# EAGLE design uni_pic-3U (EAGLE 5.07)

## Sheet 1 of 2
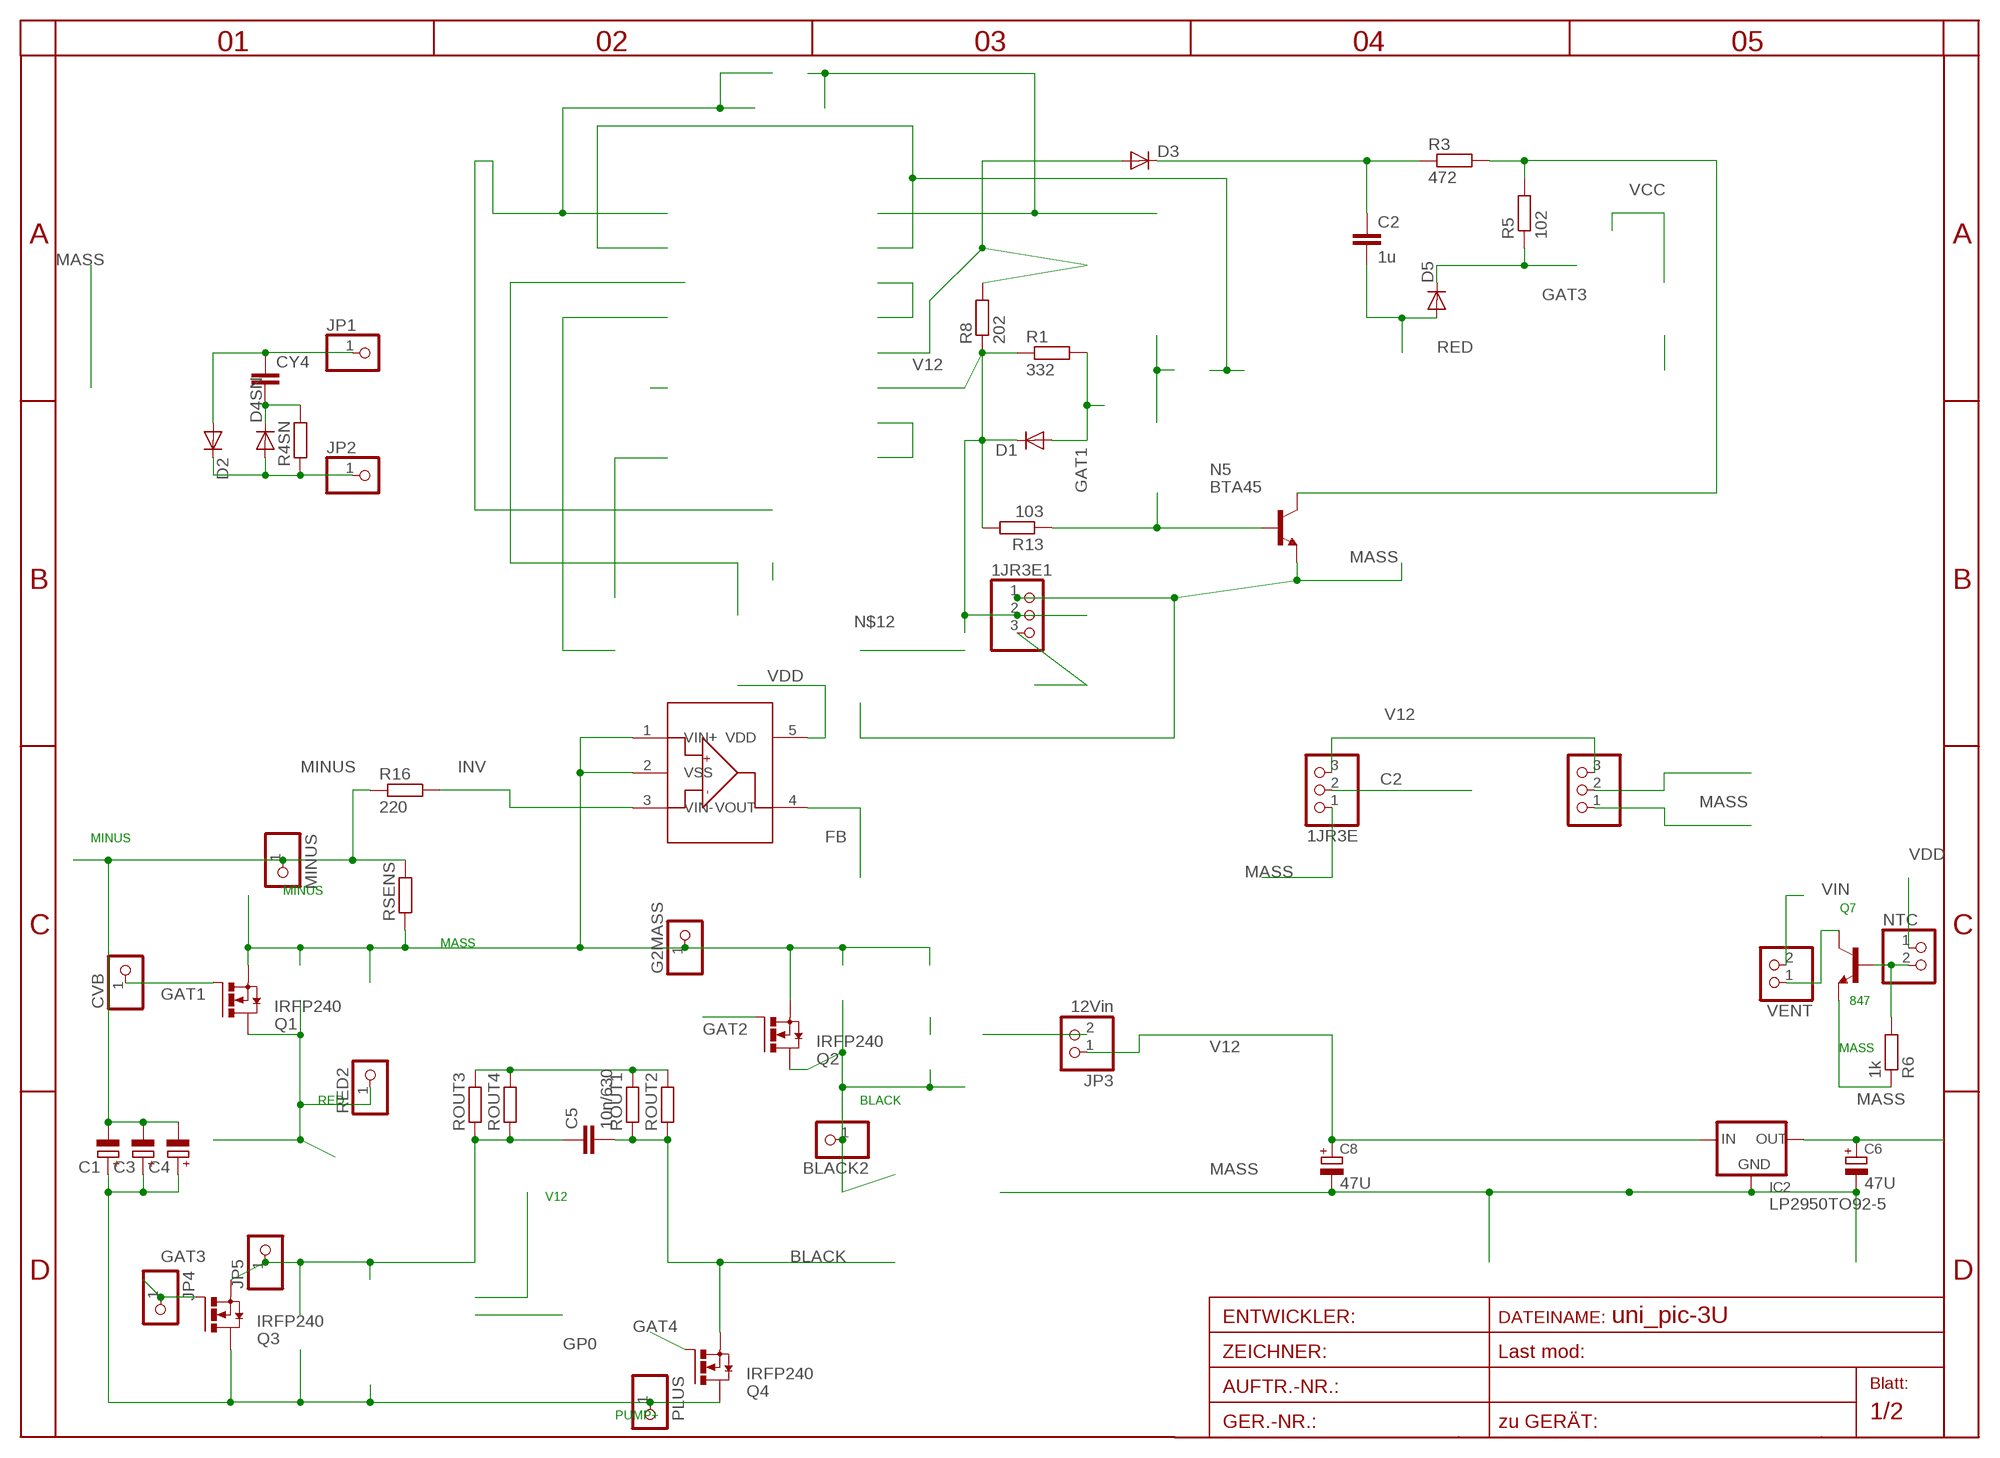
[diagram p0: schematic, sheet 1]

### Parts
1JR3E  PINHD-1X3  [1X03]
1JR3E1  PINHD-1X3  [1X03]
2JR4E3  PINHD-1X3  [1X03]
BLACK2  PINHD-1X12MM3  [1X2MM3]
C1  CPOL-EUE5-13  [E5-13]
C2  1u  C-EUC1206  [C1206]
C3  CPOL-EUE5-13  [E5-13]
C4  CPOL-EUE5-13  [E5-13]
C5  10n/630  C-EU075-042X103  [C075-042X103]
C6  47U  CPOL-EUE2.5-6  [E2,5-6]
C8  47U  CPOL-EUE2.5-6  [E2,5-6]
CVB  PINHD-1X11MM0  [1X1MM0]
CY4  CXXC10B5  [XC10B5]
D1  DIODE-MINIMELF  [MINIMELF]
D2  DIODE-SMC  [SMC]
D3  DIODE-SMA-DO214  [SMA-DO214AC]
D4SN  DIODE-P1-10  [P1-10]
D5  DIODE-MINIMELF  [MINIMELF]
G2MASS  PINHD-1X11MM0  [1X1MM0]
IC2  LP2950TO92-5  [T092-5]
JP1  PINHD-1X11MM0  [1X1MM0]
JP2  PINHD-1X11MM0  [1X1MM0]
JP3  12Vin  PINHD-1X2STR  [1X02]
JP4  PINHD-1X11MM0  [1X1MM0]
JP5  PINHD-1X11MM0  [1X1MM0]
MINUS  PINHD-1X12MM3  [1X2MM3]
N5  BTA45  SMBTA45HV  [SOT23HV]
NTC  PINHD-1X2STR  [1X02]
OP1  MCP6001U  [SOT23-5L]
PLUS  PINHD-1X12MM3  [1X2MM3]
Q1  IRFP240  [TO247BV]
Q2  IRFP240  [TO247BV]
Q3  IRFP240  [TO247BV]
Q4  IRFP240  [TO247BV]
Q7  847  BC847ALT1SMD  [SOT23]
R1  332  R-EU_R0805  [R0805]
R3  472  R-EU_R0805  [R0805]
R4SN  R-EU_0207/10  [0207/10]
R5  102  R-EU_R1206  [R1206]
R6  1k  R-EU_R0805  [R0805]
R8  202  R-EU_R0805  [R0805]
R13  103  R-EU_0207/15  [0207/15]
R16  220  R-EU_0207/30  [0207/30]
RED2  PINHD-1X12MM3  [1X2MM3]
ROUT1  R-EU_0204/7  [0204/7]
ROUT2  R-EU_0204/7  [0204/7]
ROUT3  R-EU_0204/7  [0204/7]
ROUT4  R-EU_0204/7  [0204/7]
RSENS  R-EU_0204/7  [0204/7]
VENT  PINHD-1X2STR  [1X02]

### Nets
BLACK: BLACK2.1 C5.2 Q2.D Q4.S ROUT1.1 ROUT2.1
C1: 2JR4E3.2 ; also sheet 2
C2: 1JR3E1.2 1JR3E.2 D1.C R1.1 R8.1 R13.2 ; also sheet 2
DRAIN: D2.C D4SN.A JP2.1 R4SN.1
FB: OP1.4(VOUT) ; also sheet 2
GAT1: CVB.1 D1.A Q1.G R1.2
GAT2: Q2.G
GAT3: D5.C JP4.1 Q3.G R5.1
GAT4: Q4.G
INV: OP1.3(VIN-) R16.2 ; also sheet 2
MASS: 1JR3E1.1 1JR3E.1 2JR4E3.1 C6.- C8.- G2MASS.1 IC2.2(GND) JP3.2 N5.2(E) OP1.1(VIN+) OP1.2(VSS) Q1.S Q2.S Q7.2(E) R6.1 RSENS.1 ; also sheet 2
MINUS: C1.- C3.- C4.- MINUS.1 R16.1 RSENS.2
N$4: C2.1 D3.K(C) R3.1
N$7: ROUT1.2 ROUT2.2 ROUT3.2 ROUT4.2
N$8: N5.3(C) R3.2 R5.2
N$9: NTC.2 Q7.1(B) R6.2
N$10: Q7.3(C) VENT.1
N$17: N5.1(B) R13.1
PUMP+: C1.+ C3.+ C4.+ PLUS.1 Q3.D Q4.D ; also sheet 2
RED: C2.2 C5.1 D5.A JP5.1 Q1.D Q3.S RED2.1 ROUT3.1 ROUT4.1
SNUB2: CY4.2 D4SN.C R4SN.2
SOURCE: CY4.1 D2.A JP1.1
V12: 1JR3E1.3 1JR3E.3 2JR4E3.3 C8.+ D3.A IC2.3(IN) JP3.1 R8.2
VDD: C6.+ IC2.1(OUT) NTC.1 OP1.5(VDD) ; also sheet 2
VIN: VENT.2

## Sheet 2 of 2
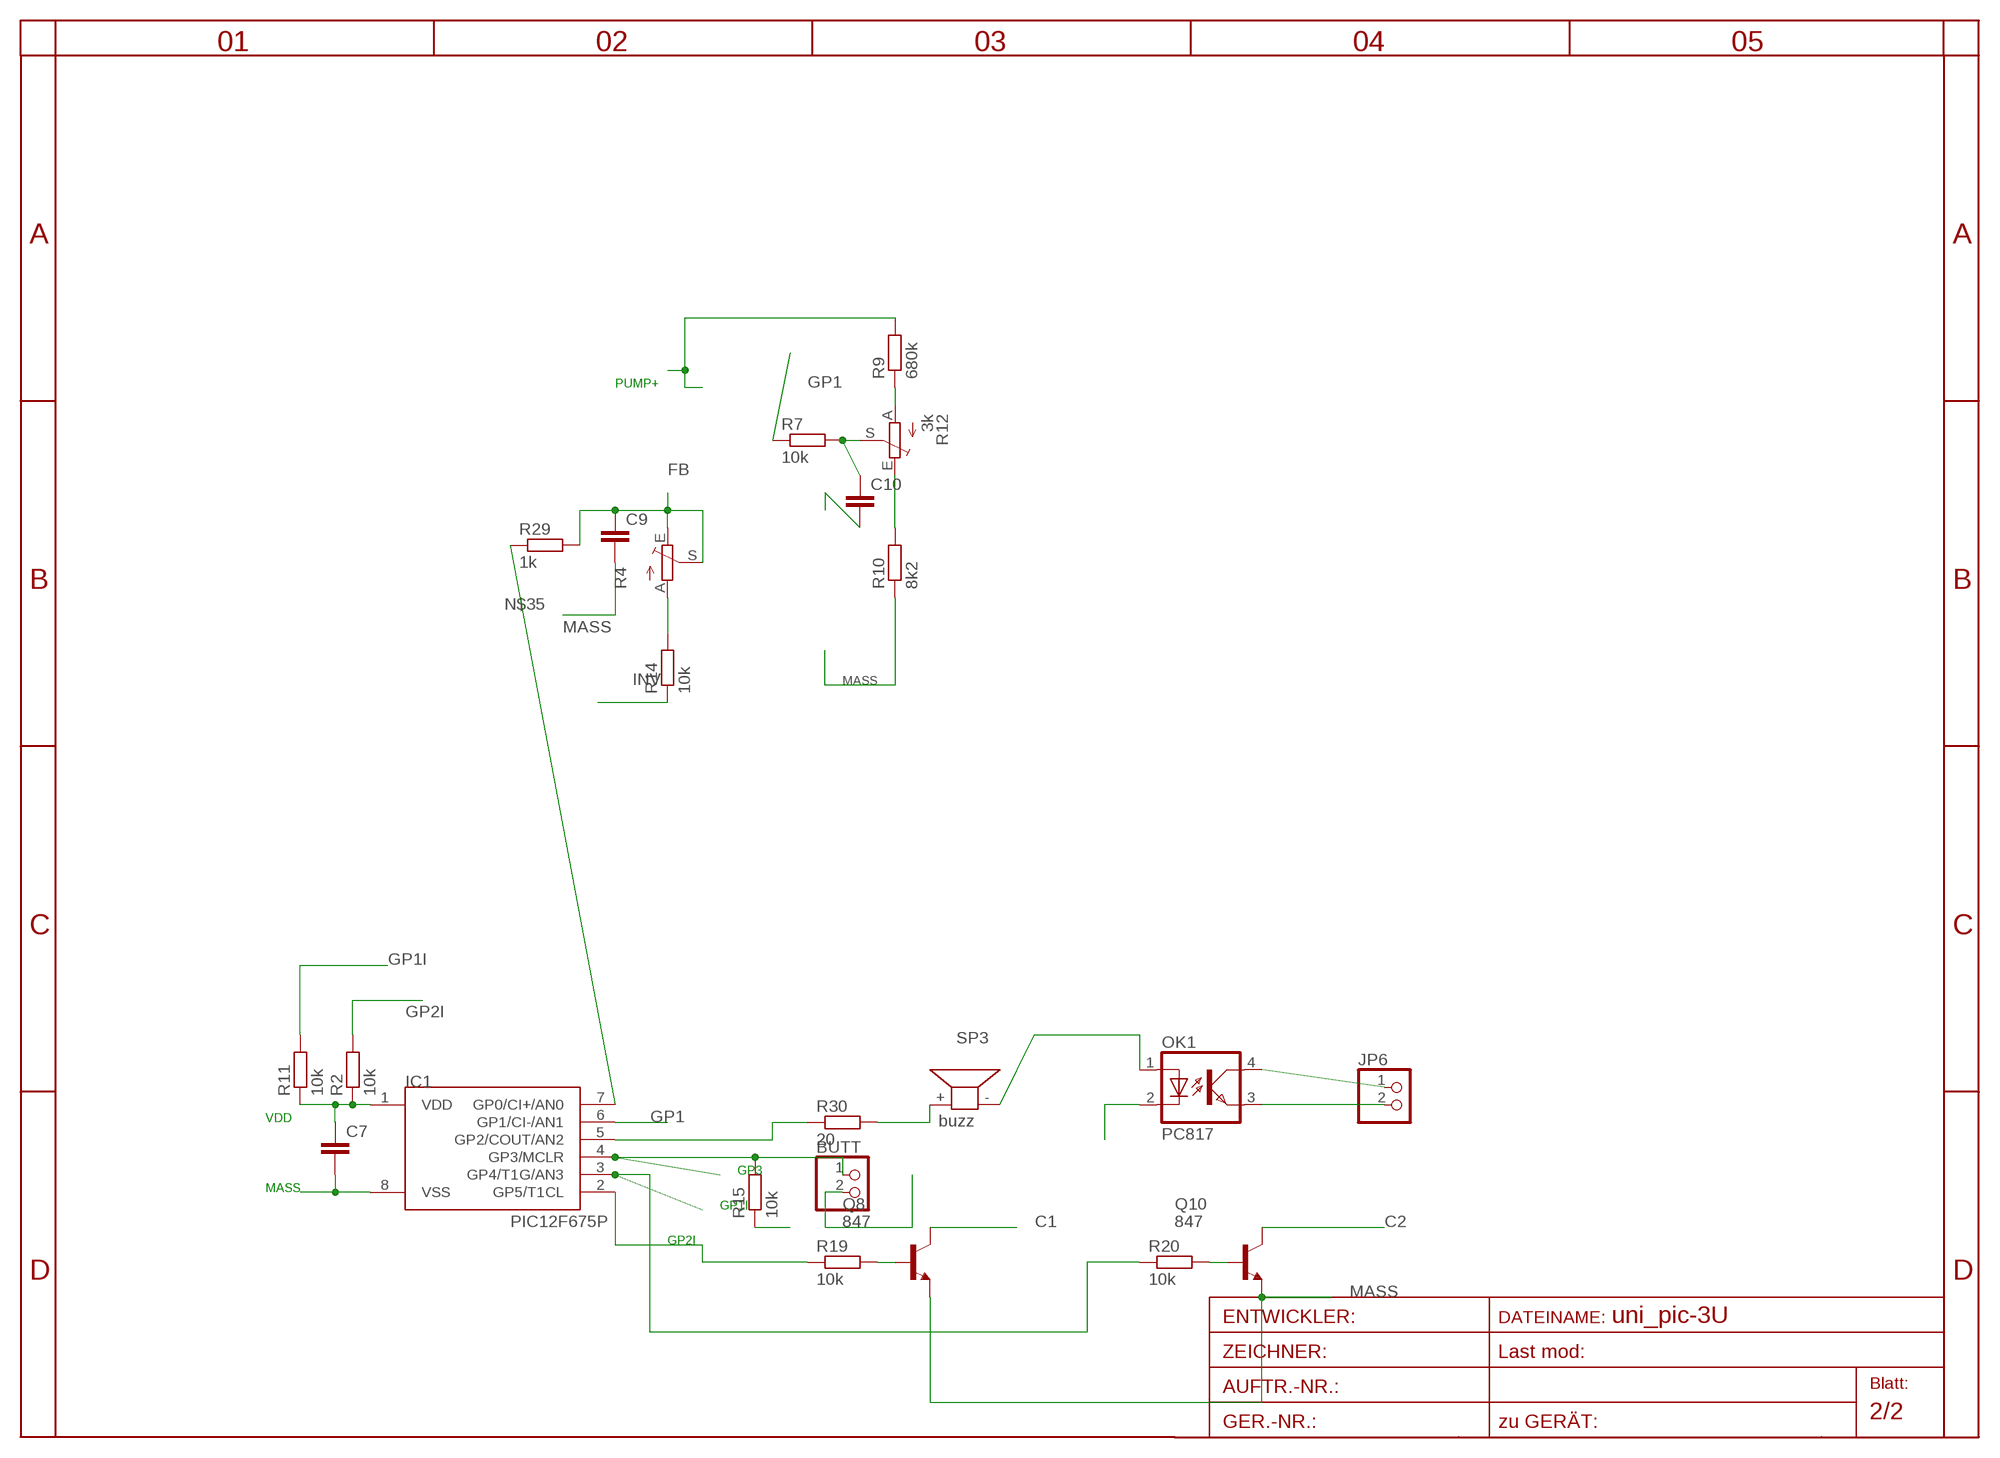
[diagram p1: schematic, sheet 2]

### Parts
BUTT  PINHD-1X2STR  [1X02]
C7  C-EUC0805  [C0805]
C9  C-EUC0805  [C0805]
C10  C-EUC0805  [C0805]
IC1  PIC12F675P  [DIL8]
JP6  PINHD-1X2STR  [1X02]
OK1  PC817  [DIL04]
Q8  847  BC847ALT1SMD  [SOT23]
Q10  847  BC847ALT1SMD  [SOT23]
R2  10k  R-EU_R0805  [R0805]
R4  TRIM_EU-CA6V  [CA6V]
R7  10k  R-EU_R0805  [R0805]
R9  680k  R-EU_0207/30  [0207/30]
R10  8k2  R-EU_R0805  [R0805]
R11  10k  R-EU_R0805  [R0805]
R12  3k  TRIM_EU-CA6V  [CA6V]
R14  10k  R-EU_R0805  [R0805]
R15  10k  R-EU_R0805  [R0805]
R19  10k  R-EU_R0805  [R0805]
R20  10k  R-EU_R0805  [R0805]
R29  1k  R-EU_R0805  [R0805]
R30  20  R-EU_R0805  [R0805]
SP3  buzz  KSS12017MM  [KSS1202]

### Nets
C1: Q8.3(C) ; also sheet 1
C2: Q10.3(C) ; also sheet 1
FB: C9.1 R4.E R4.S R29.2 ; also sheet 1
GP0I: IC1.5(GP2/COUT/AN2) R30.1
GP1: IC1.6(GP1/CI-/AN1) R7.1
GP1I: IC1.3(GP4/T1G/AN3) R11.2 R20.1
GP2I: IC1.2(GP5/T1CL) R2.2 R19.1
GP3: BUTT.1 IC1.4(GP3/MCLR) R15.2
INV: R14.1 ; also sheet 1
MASS: BUTT.2 C7.2 C9.2 C10.2 IC1.8(VSS) OK1.2(C) Q8.2(E) Q10.2(E) R10.1 ; also sheet 1
N$1: R4.A R14.2
N$5: JP6.2 OK1.3(EMIT)
N$22: Q10.1(B) R20.2
N$28: Q8.1(B) R19.2
N$29: R10.2 R12.E
N$30: R9.1 R12.A
N$31: C10.1 R7.2 R12.S
N$32: JP6.1 OK1.4(COL)
N$33: R30.2 SP3.+
N$34: OK1.1(A) SP3.-
N$35: IC1.7(GP0/CI+/AN0) R29.1
PUMP+: R9.2 ; also sheet 1
VDD: C7.1 IC1.1(VDD) R2.1 R11.1 R15.1 ; also sheet 1

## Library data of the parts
1JR3E 1JR3E1 2JR4E3 = pinhead:PINHD-1X3: PIN HEADER
BLACK2 CVB G2MASS JP1 JP2 JP4 JP5 MINUS PLUS RED2 = pinhead:PINHD-1X1: PIN HEADER
BUTT JP3 JP6 NTC VENT = pinhead:PINHD-1X2: PIN HEADER
C1 C3 C4 = rcl:CPOL-EU: POLARIZED CAPACITOR, European symbol
C2 C5 C7 C9 C10 = rcl:C-EU: CAPACITOR, European symbol
C6 C8 = rcl-2:CPOL-EU: POLARIZED CAPACITOR, European symbol
CY4 = rcl:CX: X CAPACITOR
D1-D3 D4SN D5 = diode:DIODE-: DIODE
IC1 = microchip-5:PIC12F6*: uPC nW 1k Program Flash memory 2x Timer Comparator 10b A/D converter/ 4xIN
IC2 = v-reg:LP2950?*: Source: http://cache.national.com/ds/LP/LP2950.pdf
N5 = transistor-npn:SMBTA45
OK1 = optocoupler:PC817: SHARP OPTO COUPLER
OP1 = microchip-3:MCP6001U
Q1-Q4 = transistor-power:IRFP240: HEXFET Power MosFet Source: http://www.irf.com/
Q7 Q8 Q10 = transistor-npn:BC847*: NPN Transistor
R1 R3 R4SN R5 R6 R8 R13 R14 ROUT1-ROUT4 RSENS = rcl:R-EU_: RESISTOR, European symbol
R2 R7 R9-R11 R15 R16 R19 R20 R29 R30 = rcl-2:R-EU_: RESISTOR, European symbol
R4 R12 = pot:TRIM_EU-: POTENTIOMETER
SP3 = buzzer:KSS1201: SPEAKER

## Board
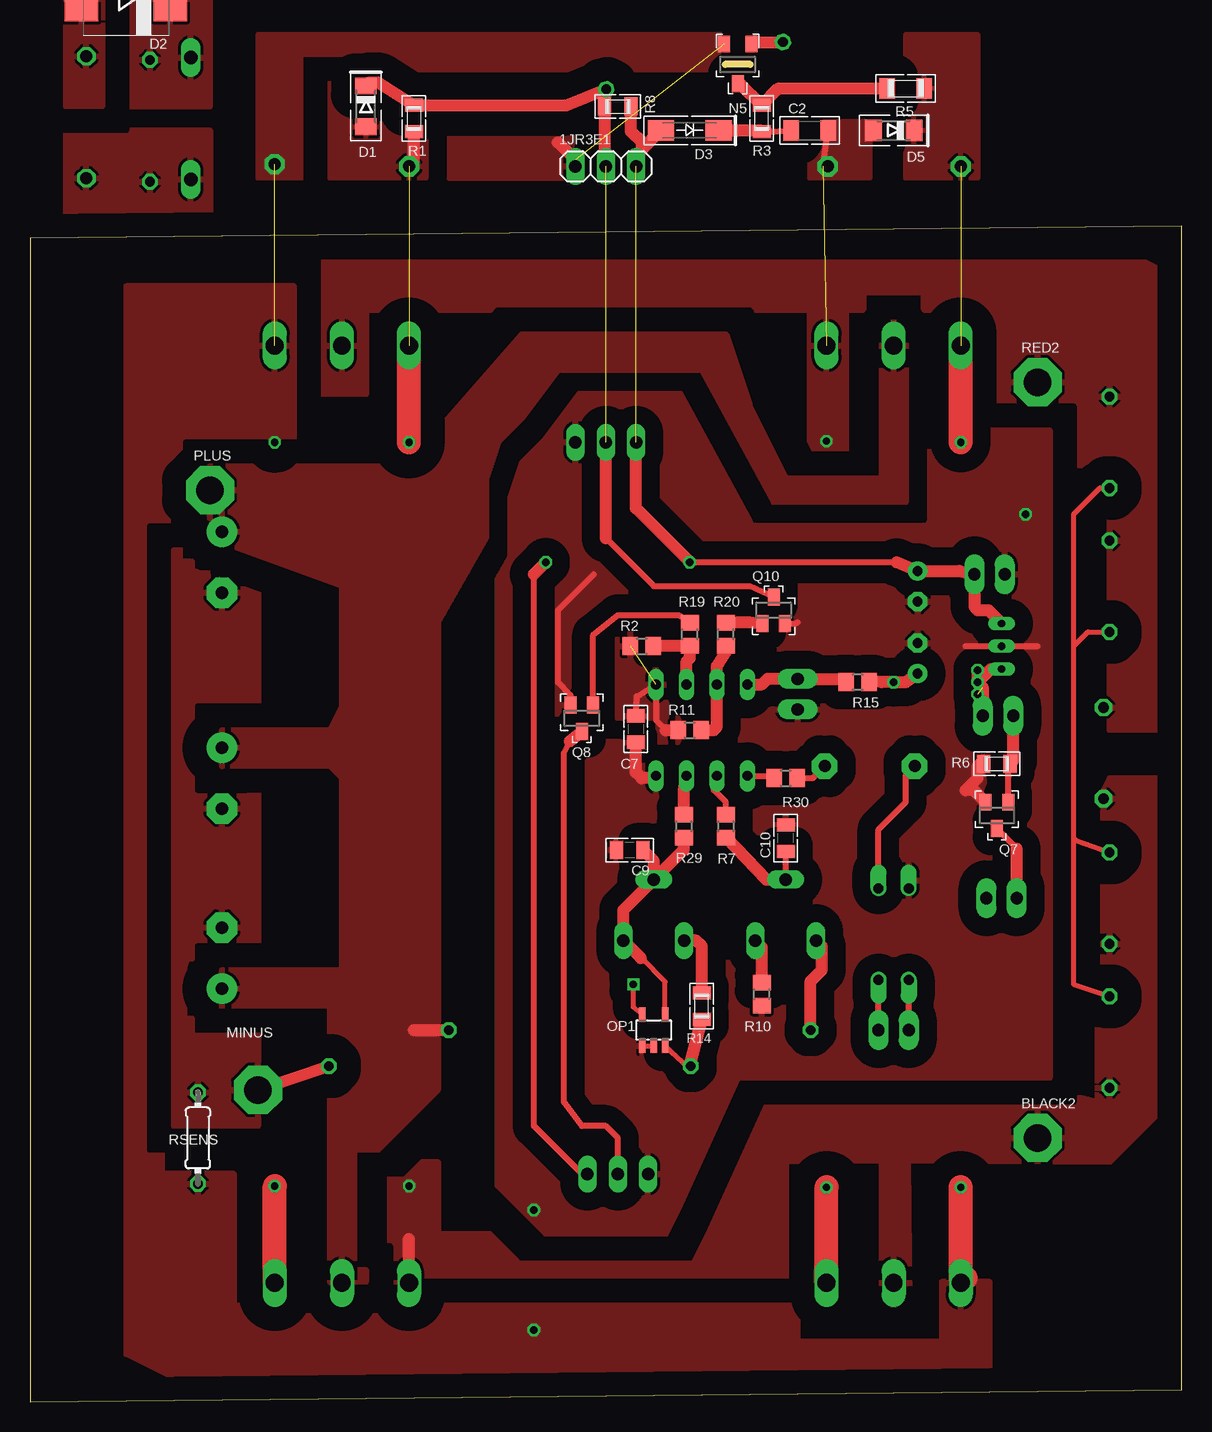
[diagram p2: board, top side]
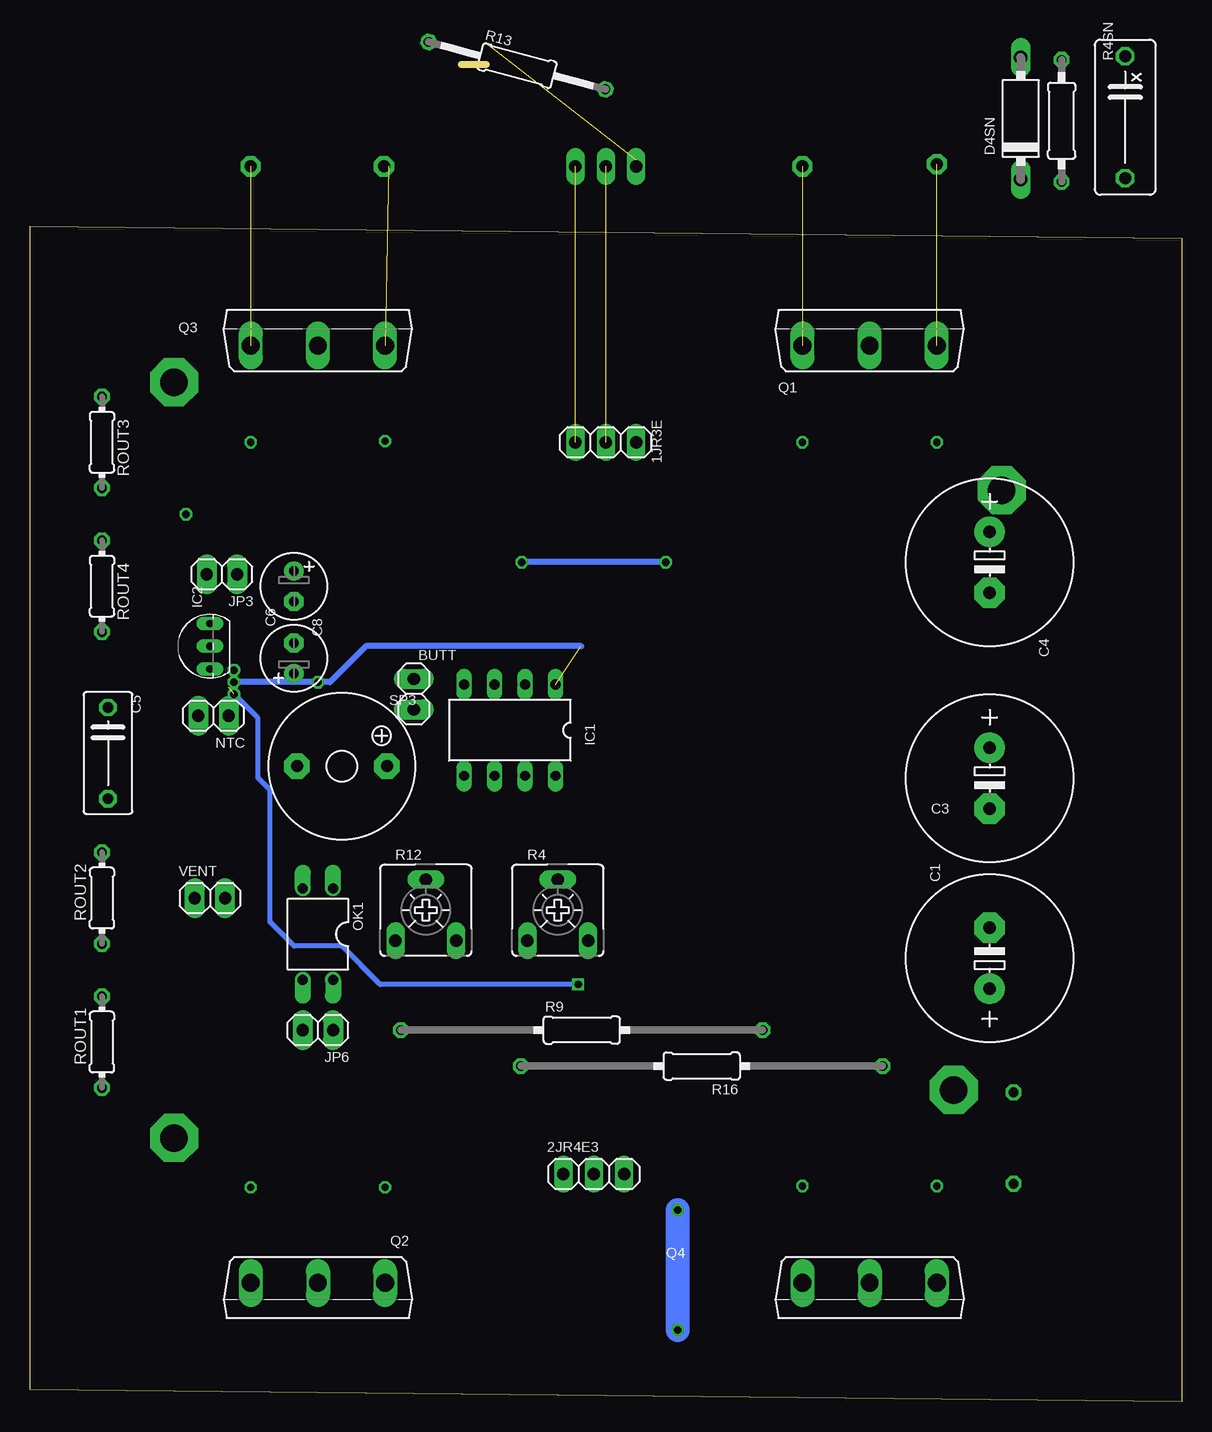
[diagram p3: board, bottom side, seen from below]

Size 96 x 98 mm. Coordinates in mm from the lower left corner, seen from the top.
Outline: 0,0 96,1 96,98 0,97 0,0
Copper layers (1*16): Top 0.035mm / dielectric 1.5mm / Bottom 0.035mm
Design rules "default *": minimum track width 10mil, minimum drill 20mil, track to track 8mil, track to pad 8mil, pad to pad 8mil, via to via 8mil, smd to smd 8mil, copper to edge 40mil, drill to drill 8mil, minimum pad ring 10mil, minimum via ring 8mil, stop-mask expansion 4mil, vias tented up to drill 0mil, thermal gap 10mil

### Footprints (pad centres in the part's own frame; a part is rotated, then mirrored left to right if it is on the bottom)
1X03 = drill 1.016 long: 1 -2.54,0; 2 0,0; 3 2.54,0
1X2MM3 = drill 2.3 pad 4 octagon: 1 0,0
1X02 = drill 1.016 pad 1.676 long: 1 -1.27,0; 2 1.27,0
E5-13 = drill 1.016 pad 2.54 round: + -2.54,0 | drill 1.016 pad 2.54 octagon: - 2.54,0
C1206 = smd 1.3 x 1.7: 1 -1.55,0; 2 1.55,0
C075-042X103 = drill 0.914 octagon: 1 -3.81,0; 2 3.81,0
E2,5-6 = drill 0.813 pad 1.6 round: + -1.27,0 | drill 0.813 pad 1.6 octagon: - 1.27,0
C0805 = smd 1.1 x 1.5: 1 -1.1,0; 2 1.1,0
1X1MM0 = drill 1 pad 1.676 octagon: 1 0,0
XC10B5 = drill 1.016 octagon: 1 -5.08,0; 2 5.08,0
MINIMELF = smd 1.4 x 1.8: A 1.7,0; C -1.7,0
SMC = smd 2.8 x 3.8: A 3.7,0; C -3.7,0
SMA-DO214AC = smd 2.2 x 1.7: A 2.4,0; K -2.4,0
P1-10 = drill 1.118 long: A 5.08,0; C -5.08,0
DIL8 = drill 0.8 long: 1 -3.81,-3.81; 2 -1.27,-3.81; 3 1.27,-3.81; 4 3.81,-3.81; 5 3.81,3.81; 6 1.27,3.81; 7 -1.27,3.81; 8 -3.81,3.81
T092-5 = drill 0.6 pad 0.813 long: 1 -1.905,0; 2 0,0; 3 1.905,0
SOT23HV = smd 1 x 1.4: 1 -1.15,-1.7; 2 1.15,-1.7; 3 0,1.6
DIL04 = drill 0.813 offset: 1 -1.27,-3.81; 2 1.27,-3.81; 3 1.27,3.81; 4 -1.27,3.81
SOT23-5L = smd 0.55 x 1.2: 1 -0.95,-1.3; 2 0,-1.3; 3 0.95,-1.3; 4 0.95,1.3; 5 -0.95,1.3
TO247BV = drill 1.499 long: D 0,-2.921; G -5.588,-2.921; S 5.588,-2.921
SOT23 = smd 1 x 1.4: 1 -0.95,-1.1; 2 0.95,-1.1; 3 0,1.1
R0805 = smd 1.1 x 1.5: 1 -1.1,0; 2 1.1,0
R0805' = smd 1.3 x 1.5: 1 -0.95,0; 2 0.95,0
CA6V = drill 1.016 long: A -2.54,-2.54; E 2.54,-2.54; S 0,2.54
0207/10 = drill 0.813 octagon: 1 -5.08,0; 2 5.08,0
R1206 = smd 1.3 x 1.7: 1 -1.55,0; 2 1.55,0
0207/30 = drill 0.813 octagon: 1 -15.08,0; 2 15.08,0
0207/15 = drill 0.813 octagon: 1 -7.62,0; 2 7.62,0
0204/7 = drill 0.813 octagon: 1 -3.81,0; 2 3.81,0
KSS1202 = drill 1 pad 2.159 octagon: + 3.75,0; - -3.75,0

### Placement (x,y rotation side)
1JR3E  48,80 180 bottom
1JR3E1  48,103 0 top  (outside the outline)
2JR4E3  49,19 0 bottom
BLACK2  84,22 0 top
BUTT  64,59 270 bottom
C1  16,37 90 bottom
C2  65,106 0 top  (outside the outline)
C3  16,52 270 bottom
C4  16,70 270 bottom
C5  89.5,54.1 270 bottom
C6  74,62 90 bottom
C7  50.5,56.1 270 top
C8  74,68 270 bottom
C9  50,46 180 top
C10  63,47 90 top
CVB  31.6,103 0 top  (outside the outline)
CY4  not placed on the board
D1  28,108 270 top  (outside the outline)
D2  not placed on the board
D3  55,106 180 top  (outside the outline)
D4SN  not placed on the board
D5  not placed on the board
G2MASS  not placed on the board
IC1  56,56 180 bottom
IC2  81,63 90 bottom
JP1  not placed on the board
JP2  not placed on the board
JP3  80,69 180 bottom
JP4  not placed on the board
JP5  66.5,103 180 top  (outside the outline)
JP6  72,31 180 bottom
MINUS  19,26 0 top
N5  59,111.5 180 top  (outside the outline)
NTC  80.7,57.2 180 bottom
OK1  72,39 180 bottom
OP1  52,31 0 top
PLUS  15,76 0 top
Q1  26,91 0 bottom
Q2  72,7 180 bottom
Q3  72,91 0 bottom
Q4  26,7 180 bottom
Q7  80.6,48.9 180 top
Q8  46,57 180 top
Q10  62,66 0 top
R1  32,107 270 top  (outside the outline)
R2  10k  [R0805']  51,63 0 top
R3  61,107 90 top  (outside the outline)
R4  52,41 0 bottom
R4SN  not placed on the board
R5  73,109.5 180 top  (outside the outline)
R6  80.6,53.2 0 top
R7  10k  [R0805']  58,48 270 top
R8  49,108 0 top  (outside the outline)
R9  50,31 0 bottom
R10  8k2  [R0805']  61,34 90 top
R11  10k  [R0805']  55,56 0 top
R12  63,41 0 bottom
R13  55.4,111.4 345 bottom  (outside the outline)
R14  56,33 90 top
R15  10k  [R0805']  69,60 180 top
R16  40,28 180 bottom
R19  10k  [R0805']  55,64 90 top
R20  10k  [R0805']  58,64 90 top
R29  1k  [R0805']  54.5,48 270 top
R30  20  [R0805']  63,52 0 top
RED2  84,85 0 top
ROUT1  90,30 90 bottom
ROUT2  90,42 90 bottom
ROUT3  90,80 270 bottom
ROUT4  90,68 270 bottom
RSENS  14,22 90 top
SP3  70,53 0 bottom
VENT  81,42 0 bottom

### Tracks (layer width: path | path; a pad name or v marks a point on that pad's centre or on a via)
BLACK  (via drill 0.6 pad 1)
  Top 1: Q4.S 31.59,13.59
  other vias: 31.6,18
  pour Top (isolate 2, rank 4): 30,20 34,20 34,14 55,14 61,26 85,26 89,25 89,50 90,52 96,52 96,26 90,20 85,20 73.2,20.1 73.3,8.1 71,8.1 71,20.1 63,20 63,10 30,10
C1
  Top 0.5: 2JR4E3.2 49,22 48,23 46,23 44.5,25 44.5,54.1 45,55.1
  Top 1.016: 45,55.1 Q8.3
C2  (1 unrouted)
  Top 0.5: Q10.3 60,68 52,68 48,72
  Top 1: D1.C 28.3,110 29,110 R1.1 44.71,108.1 R13.2 47.9,109 R8.1 47.9,103.1 1JR3E1.2
  Top 1.016: 48,72 1JR3E.2
DRAIN
  pour Top (isolate 2, rank 2): 8,122 8,108 15,108 15,122
FB
  Top 0.406: OP1.4 52.95,35.05 51,37 50.92,37
  Top 1: C9.1 52,45.1 R4.S | R29.2 54.5,46.04 R4.S | 50.92,37 R4.E 49.46,41 R4.S
GAT1  (via drill 0.6 pad 1)  (1 unrouted)
  Top 1: R1.2 32,103.4 CVB.1
  Top 2: Q1.G v31.6,80
  pour Top (isolate 2): 25,102 25,110 33,110 33,102
GAT2  (via drill 0.6 pad 1)
  Top 2: Q2.G v66.4,17.9
GAT3  (via drill 0.6 pad 1)  (1 unrouted)
  Top 2: v77.6,80 77.59,80 Q3.G
  pour Top (isolate 2, rank 2): 73,114 79,114 79,102 73,102
GAT4  (via drill 0.6 pad 1)
  Top 2: Q4.G v20.4,18
GP0I
  Top 0.5: IC1.5 61.71,52.19 R30.1
GP1
  Top 0.5: R7.1 58,50 57,51 57,51.92 IC1.6
GP1I
  Top 1: R20.1 58,62.5 57.27,61.33 IC1.3 57.27,56.27 57,56 R11.2
GP2I
  Top 1: IC1.2 54.73,61.73 55,62 R19.1 54.9,63 R2.2
GP3
  Top 1: IC1.4 61.01,59.81 61.5,60.3 63.97,60.3 BUTT.1 67.63,60.27 R15.2
INV
  Top 0.406: 55,28.08 R16.2 54.95,27.87 OP1.3
  Top 1: 55,28.08 R14.1
MASS  (via drill 0.6 pad 1)  (2 unrouted)
  Top 0.406: OP1.1 OP1.2
  Top 0.5: 78,63 IC2.2 84,63 | Q10.2 63.9,64.9 64,65 | Q8.2 45.05,58.95 44,60 44,66 47,69
  Top 1: C7.2 50.5,52.5 51,52 52,52 IC1.8 | 1JR3E1.1 45.46,103.54 44,105 | R6.1 79.2,53.2 79,53 79,52 78,51 78.65,51 Q7.2 | Q2.S 78,10.33
  Top 2: 78,10.33 77.6,10.33 v77.6,17.9
  Bottom 2: v42,6 v42,16
  other vias: 83,74 20.4,80
  pour Top (isolate 1.5, rank 3): 39,18 39,79 44,85 54,85 55,84 56,81 60,75 73,75 73,81 85,81 85,27 59,27 54,16 53,14 43,14
  pour Top (isolate 2, rank 2, no thermals): 19,114 65,114 65,111 23,111 23,102 19,102
  pour Top (isolate 2, rank 3): 22,93 8,93 8,4 12,2 80,2 80,10 76,10 76,5 64,5 64,8 17,8 17,19 11,19 11,71 22,71
  pour Top (isolate 2): 35,107 46,107 46,102 35,102
MINUS
  Top 1: MINUS.1 R16.1
  pour Top (isolate 2, rank 2): 12,71 19,71 19,23 12,23
N$1
  Top 1: R4.A 55.54,38.46 56,38 R14.2
N$4
  Top 0.5: C2.1 61.8,105.9 R3.1
  Top 1: D3.K 60.9,106 R3.1
N$5
  Top 0.5: JP6.2 OK1.3
N$7
  Top 0.406: 87,47 87,34.81 ROUT1.2 | ROUT2.2 87.19,46.81 87,47 | ROUT3.2 89.19,76.19 87,74 87,63 | 87,47 87,63 | ROUT4.2 88.19,64.19 87,63
N$8
  Top 1: R5.2 62.4,109.5 R3.2 59.2,109.9 N5.3
N$9
  Top 0.5: 81.97,53.47 R6.2 81.55,53.05 Q7.1
  Top 1: 81.97,53.47 NTC.2
N$10
  Top 0.5: 82.27,46.13 Q7.3
  Top 1: VENT.1 82.27,46.13
N$17
  Top 1: R13.1 60.32,113.37 N5.1
N$22
  Top 1: R20.2 59,65 59.95,65 Q10.1
N$28
  Top 0.5: Q8.1 46.95,63.95 49,65.6 54.1,65.6 R19.2
N$29
  Top 0.5: 61,37.92 R12.E
  Top 1: R10.2 61,37.92
N$30
  Top 0.5: 65.5,35.5 65,35 | 66,38 R12.A
  Top 1: 66,38 66,36 65.5,35.5 65.08,35.08 R9.1
N$31
  Top 0.5: R12.S C10.1
  Top 1: R12.S 61.36,43.54 R7.2
N$32
  Top 0.5: JP6.1 OK1.4
N$33
  Top 0.5: R30.2 65.25,52 SP3.+
N$34
  Top 0.5: OK1.1 70.73,47.73 73,50 73,52.25 SP3.-
N$35
  Top 1: R29.1 54.5,50.96 IC1.7
PUMP+
  Top 1: 32,31 R9.2
  pour Top (isolate 2): 26,68 15,72 15,78 34,78 34,81 41,89 58,89 60,83 63,77 71,77 71,90 73,90 73,75 62,75 56,86 44,86 41,82 39,80 38,77 38,72 34,65 34,26 29,21 27,21 27,11 28,11 28,10 25,10 25,33 15,33 16,36 26,36 26,52 25,53 16,53 16,56 25,56 26,58
RED  (via drill 0.6 pad 1)  (1 unrouted)
  Top 0.5: C2.2 66.1,103 JP5.1 67,103
  Top 1: Q3.S 66,87.67
  other vias: 66.4,80.1
  pour Top (isolate 2, no thermals): 65,107 70,107 70,102 65,102
  pour Top (isolate 2, rank 4): 28,84 24,84 24,95 93,95 95,94 96,93 97,56 90,56 90,76 80,84 80,91 68,91 68,79 65,79 65,91 28,91
SNUB2
  pour Top (isolate 2, rank 2): 3,106 15,106 15,99 3,99
SOURCE
  pour Top (isolate 2): 3,122 6,122 6,108 3,108
V12  (via drill 0.6 pad 1)  (1 unrouted)
  Top 0.5: 2JR4E3.3 46,19 42,23 42,69 | v55,70 72.27,70
  Top 1: v55,70 50.5,74.5 50.5,79.96 1JR3E.3 | 72.27,70 C8.+ 77.46,69.27 JP3.1 78.73,66.27 79,66 79.91,66 IC2.3 | 42,69 v43,70 | 1JR3E1.3 50.54,103.94 51,104.4 | 51,104.4 D3.A | R8.2 50.1,105.9 51,105 51,104.4
  Bottom 0.5: v43,70 v55,70
VDD  (via drill 0.6, 0.6 pad 1)  (3 unrouted)
  Top 0.35: R11.1 54.05,55.95
  Top 0.406: OP1.5 50.3,32.9 v50.3,34.8
  Top 0.5: 53,56 52.19,56.81 IC1.1 50.6,58.82 C7.1 | 80.09,61.09 IC2.1
  Top 1: 53,56 R11.1 | C6.+ 73,60 v72,60 71,60 70.1,60.1 R15.1 | v79,60 80.09,61.09 | NTC.1 79.43,59.57 v79,60 | v79,60 v79,61
  Bottom 0.406: v50.3,34.8 66.8,34.8 70,38 74,38 76,40 76,51 77,52 77,57 v79,59
  Bottom 0.5: v79,60 v72,60 71,60 68,63 R2.1
  pour Top (isolate 1.016): 49,64 51,64 51,61 53,61 53,57 54,57 54,55 52.4,55 52.4,57 49,57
